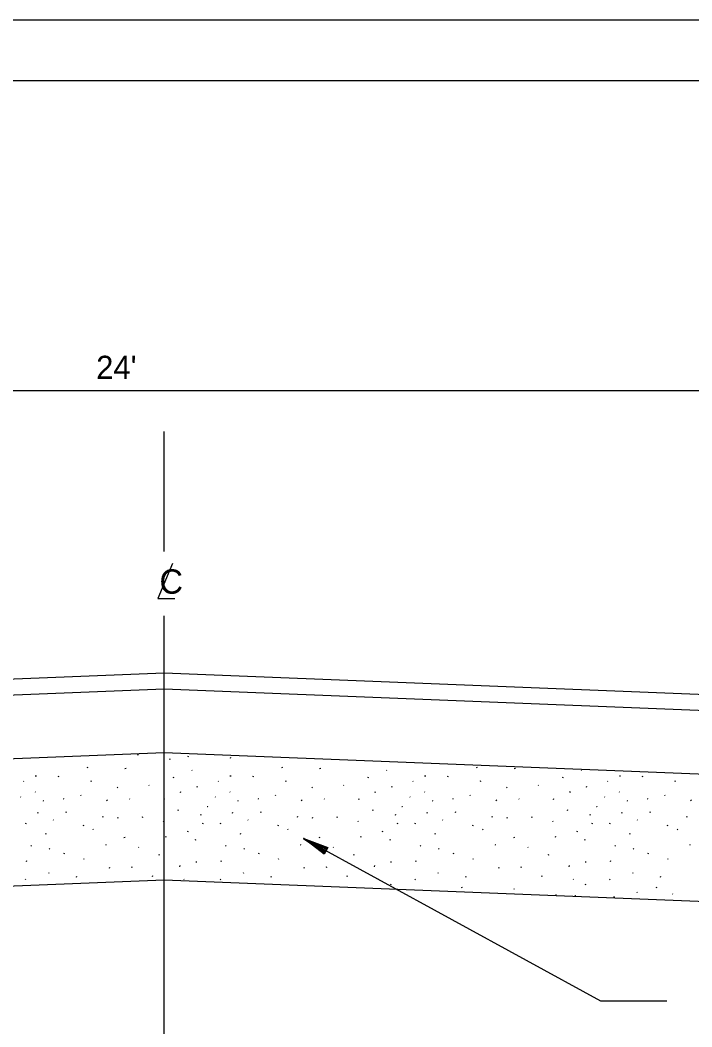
# Model space of a CAD drawing. Extents: x 29.7 to 46.4, y -39.2 to -28.2.
# Drawn here: x 40.593 to 43.008, y -31.812 to -28.193 of the extents above; entities that cross this region are included whole.
import ezdxf

# ---------------------------------------------------------------- set-up
doc = ezdxf.new("R2010")
doc.units = 0
for name, color, linetype in [('Level 11', 7, 'Continuous'), ('Level 6', 7, 'Continuous'), ('Level 60', 7, 'Continuous'), ('Level 8', 7, 'Continuous'), ('Level 9', 7, 'Continuous')]:
    doc.layers.add(name, color=color, linetype=linetype)

msp = doc.modelspace()

# ---------------------------------------------------------------- linework, layer by layer
at = {"layer": 'Level 11'}
msp.add_line((38.3762, -29.5241), (43.845, -29.5241), dxfattribs=at)
at = {"layer": 'Level 6'}
for p, q in [((41.1106, -30.1026), (41.1106, -29.672)), ((41.1106, -31.9659), (41.1106, -30.334)), ((41.1106, -30.5401), (38.3762, -30.6495)), ((43.845, -30.6495), (41.1106, -30.5401)), ((41.1106, -30.5974), (38.3762, -30.7068)), ((43.845, -30.7068), (41.1106, -30.5974)), ((41.1106, -30.8264), (38.3762, -30.9358)), ((41.0156, -30.8355), (41.0169, -30.8319)), ((43.845, -30.9358), (41.1106, -30.8264)), ((40.6492, -30.8457), (40.6495, -30.8449)), ((41.133, -30.8493), (41.1293, -30.8501)), ((41.1972, -30.8406), (41.1984, -30.837)), ((41.3492, -30.8457), (41.3505, -30.8421)), ((40.8362, -30.8798), (40.8324, -30.8806)), ((40.9736, -30.8832), (40.9698, -30.884)), ((41.2118, -30.8904), (41.21, -30.8886)), ((41.5362, -30.8798), (41.5324, -30.8806)), ((41.6736, -30.8832), (41.6698, -30.884)), ((41.9118, -30.8904), (41.91, -30.8886)), ((42.2362, -30.8798), (42.2324, -30.8806)), ((42.3736, -30.8832), (42.3698, -30.884)), ((42.6118, -30.8904), (42.61, -30.8886)), ((40.6067, -30.9301), (40.6049, -30.9283)), ((40.6513, -30.9103), (40.6475, -30.9111)), ((40.7307, -30.9134), (40.7319, -30.9098)), ((40.8498, -30.9289), (40.846, -30.9297)), ((41.0574, -30.9446), (41.0556, -30.9427)), ((41.1446, -30.9168), (41.1458, -30.9131)), ((41.3067, -30.9301), (41.3049, -30.9283)), ((41.3513, -30.9103), (41.3475, -30.9111)), ((41.4307, -30.9134), (41.4319, -30.9098)), ((41.5498, -30.9289), (41.546, -30.9297)), ((41.7574, -30.9446), (41.7556, -30.9427)), ((41.8446, -30.9168), (41.8458, -30.9131)), ((42.0067, -30.9301), (42.0049, -30.9283)), ((42.0513, -30.9103), (42.0475, -30.9111)), ((42.1307, -30.9134), (42.1319, -30.9098)), ((42.2498, -30.9289), (42.246, -30.9297)), ((42.4574, -30.9446), (42.4556, -30.9427)), ((42.5446, -30.9168), (42.5458, -30.9131)), ((42.7067, -30.9301), (42.7049, -30.9283)), ((42.7513, -30.9103), (42.7475, -30.9111)), ((42.8307, -30.9134), (42.8319, -30.9098)), ((42.9498, -30.9289), (42.946, -30.9297)), ((40.6486, -30.9683), (40.6468, -30.9664)), ((40.8126, -30.981), (40.8108, -30.9792)), ((40.9439, -30.9519), (40.9421, -30.9501)), ((41.17, -30.9693), (41.1713, -30.9656)), ((41.2295, -30.9501), (41.2307, -30.9464)), ((41.3486, -30.9683), (41.3468, -30.9664)), ((41.5126, -30.981), (41.5108, -30.9792)), ((41.6439, -30.9519), (41.6421, -30.9501)), ((41.87, -30.9693), (41.8713, -30.9656)), ((41.9295, -30.9501), (41.9307, -30.9464)), ((42.0486, -30.9683), (42.0468, -30.9664)), ((42.2126, -30.981), (42.2108, -30.9792)), ((42.3439, -30.9519), (42.3421, -30.9501)), ((42.57, -30.9693), (42.5713, -30.9656)), ((42.6295, -30.9501), (42.6307, -30.9464)), ((42.7486, -30.9683), (42.7468, -30.9664)), ((42.9126, -30.981), (42.9108, -30.9792)), ((40.5958, -30.9865), (40.5939, -30.9846)), ((40.6778, -31.001), (40.6759, -30.9992)), ((40.7507, -30.9937), (40.7488, -30.9919)), ((40.9074, -30.9974), (40.9038, -30.9992)), ((40.9876, -30.9937), (40.9858, -30.9919)), ((41.1107, -30.9946), (41.1119, -30.991)), ((41.2958, -30.9865), (41.2939, -30.9846)), ((41.3778, -31.001), (41.3759, -30.9992)), ((41.4507, -30.9937), (41.4488, -30.9919)), ((41.6074, -30.9974), (41.6038, -30.9992)), ((41.6876, -30.9937), (41.6858, -30.9919)), ((41.8107, -30.9946), (41.8119, -30.991)), ((41.9958, -30.9865), (41.9939, -30.9846)), ((42.0778, -31.001), (42.0759, -30.9992)), ((42.1507, -30.9937), (42.1488, -30.9919)), ((42.3074, -30.9974), (42.3038, -30.9992)), ((42.3876, -30.9937), (42.3858, -30.9919)), ((42.5107, -30.9946), (42.5119, -30.991)), ((42.6958, -30.9865), (42.6939, -30.9846)), ((42.7778, -31.001), (42.7759, -30.9992)), ((42.8507, -30.9937), (42.8488, -30.9919)), ((43.0074, -30.9974), (43.0038, -30.9992)), ((40.6561, -31.0441), (40.6573, -31.0405)), ((40.7579, -31.0408), (40.7591, -31.0371)), ((41.1616, -31.034), (41.1628, -31.0304)), ((41.243, -31.0509), (41.2442, -31.0473)), ((41.2651, -31.0192), (41.2666, -31.02)), ((41.2666, -31.02), (41.2673, -31.0209)), ((41.3561, -31.0441), (41.3573, -31.0405)), ((41.4579, -31.0408), (41.4591, -31.0371)), ((41.8616, -31.034), (41.8628, -31.0304)), ((41.943, -31.0509), (41.9442, -31.0473)), ((41.9651, -31.0192), (41.9666, -31.02)), ((41.9666, -31.02), (41.9673, -31.0209)), ((42.0561, -31.0441), (42.0573, -31.0405)), ((42.1579, -31.0408), (42.1591, -31.0371)), ((42.5616, -31.034), (42.5628, -31.0304)), ((42.643, -31.0509), (42.6442, -31.0473)), ((42.6651, -31.0192), (42.6666, -31.02)), ((42.6666, -31.02), (42.6673, -31.0209)), ((42.7561, -31.0441), (42.7573, -31.0405)), ((42.8579, -31.0408), (42.8591, -31.0371)), ((40.6136, -31.0819), (40.6149, -31.0783)), ((40.7131, -31.0691), (40.7113, -31.0673)), ((40.8206, -31.0887), (40.8218, -31.0851)), ((40.8902, -31.0577), (40.8914, -31.0541)), ((40.9444, -31.0616), (40.9456, -31.058)), ((41.0346, -31.0585), (41.0309, -31.0593)), ((41.11, -31.0742), (41.1082, -31.0724)), ((41.2498, -31.0814), (41.2511, -31.0778)), ((41.3136, -31.0819), (41.3149, -31.0783)), ((41.4131, -31.0691), (41.4113, -31.0673)), ((41.5206, -31.0887), (41.5218, -31.0851)), ((41.5902, -31.0577), (41.5914, -31.0541)), ((41.6444, -31.0616), (41.6456, -31.058)), ((41.7346, -31.0585), (41.7309, -31.0593)), ((41.81, -31.0742), (41.8082, -31.0724)), ((41.9498, -31.0814), (41.9511, -31.0778)), ((42.0136, -31.0819), (42.0149, -31.0783)), ((42.1131, -31.0691), (42.1113, -31.0673)), ((42.2206, -31.0887), (42.2218, -31.0851)), ((42.2902, -31.0577), (42.2914, -31.0541)), ((42.3444, -31.0616), (42.3456, -31.058)), ((42.4346, -31.0585), (42.4309, -31.0593)), ((42.51, -31.0742), (42.5082, -31.0724)), ((42.6498, -31.0814), (42.6511, -31.0778)), ((42.7136, -31.0819), (42.7149, -31.0783)), ((42.8131, -31.0691), (42.8113, -31.0673)), ((42.9206, -31.0887), (42.9218, -31.0851)), ((42.9902, -31.0577), (42.9914, -31.0541)), ((40.6849, -31.1192), (40.6861, -31.1156)), ((40.8573, -31.103), (40.8554, -31.1012)), ((41.1174, -31.1293), (41.1186, -31.1257)), ((41.1955, -31.1107), (41.1967, -31.1071)), ((41.3849, -31.1192), (41.3861, -31.1156)), ((41.5573, -31.103), (41.5554, -31.1012)), ((41.8174, -31.1293), (41.8186, -31.1257)), ((41.8955, -31.1107), (41.8967, -31.1071)), ((42.0849, -31.1192), (42.0861, -31.1156)), ((42.2573, -31.103), (42.2554, -31.1012)), ((42.5174, -31.1293), (42.5186, -31.1257)), ((42.5955, -31.1107), (42.5967, -31.1071)), ((42.7849, -31.1192), (42.7861, -31.1156)), ((42.9573, -31.103), (42.9554, -31.1012)), ((40.6333, -31.1622), (40.6315, -31.1604)), ((40.9031, -31.1588), (40.9012, -31.157)), ((40.9702, -31.1313), (40.9664, -31.1321)), ((41.2247, -31.1397), (41.2209, -31.1406)), ((41.3333, -31.1622), (41.3315, -31.1604)), ((41.6031, -31.1588), (41.6012, -31.157)), ((41.6702, -31.1313), (41.6664, -31.1321)), ((41.9247, -31.1397), (41.9209, -31.1406)), ((42.0333, -31.1622), (42.0315, -31.1604)), ((42.3031, -31.1588), (42.3012, -31.157)), ((42.3702, -31.1313), (42.3664, -31.1321)), ((42.6247, -31.1397), (42.6209, -31.1406)), ((42.7333, -31.1622), (42.7315, -31.1604)), ((43.0031, -31.1588), (43.0012, -31.157)), ((40.6995, -31.1724), (40.6977, -31.1705)), ((40.751, -31.1903), (40.7522, -31.1866)), ((41.0201, -31.1673), (41.0183, -31.1655)), ((41.094, -31.1939), (41.0903, -31.1947)), ((41.3995, -31.1724), (41.3977, -31.1705)), ((41.451, -31.1903), (41.4522, -31.1866)), ((41.7201, -31.1673), (41.7183, -31.1655)), ((41.794, -31.1939), (41.7903, -31.1947)), ((42.0995, -31.1724), (42.0977, -31.1705)), ((42.151, -31.1903), (42.1522, -31.1866)), ((42.4201, -31.1673), (42.4183, -31.1655)), ((42.494, -31.1939), (42.4903, -31.1947)), ((42.7995, -31.1724), (42.7977, -31.1705)), ((42.851, -31.1903), (42.8522, -31.1866)), ((40.6153, -31.2173), (40.6165, -31.2137)), ((40.8233, -31.2096), (40.8215, -31.2078)), ((41.1666, -31.236), (41.1679, -31.2323)), ((41.2281, -31.2193), (41.2243, -31.2201)), ((41.3153, -31.2173), (41.3165, -31.2137)), ((41.5233, -31.2096), (41.5215, -31.2078)), ((41.8666, -31.236), (41.8679, -31.2323)), ((41.9281, -31.2193), (41.9243, -31.2201)), ((42.0153, -31.2173), (42.0165, -31.2137)), ((42.2233, -31.2096), (42.2215, -31.2078)), ((42.5666, -31.236), (42.5679, -31.2323)), ((42.6281, -31.2193), (42.6243, -31.2201)), ((42.7153, -31.2173), (42.7165, -31.2137)), ((42.9233, -31.2096), (42.9215, -31.2078)), ((40.6978, -31.2604), (40.696, -31.2586)), ((40.7951, -31.2732), (40.7964, -31.2696)), ((40.9139, -31.2411), (40.9151, -31.2374)), ((40.9956, -31.2379), (40.9919, -31.2387)), ((41.0683, -31.2715), (41.0695, -31.2679)), ((41.3978, -31.2604), (41.396, -31.2586)), ((41.4951, -31.2732), (41.4964, -31.2696)), ((41.6139, -31.2411), (41.6151, -31.2374)), ((41.6956, -31.2379), (41.6919, -31.2387)), ((41.7683, -31.2715), (41.7695, -31.2679)), ((42.0978, -31.2604), (42.096, -31.2586)), ((42.1951, -31.2732), (42.1963, -31.2696)), ((42.3139, -31.2411), (42.3151, -31.2374)), ((42.3956, -31.2379), (42.3919, -31.2387)), ((42.4683, -31.2715), (42.4695, -31.2679)), ((42.7978, -31.2604), (42.796, -31.2586)), ((42.8951, -31.2732), (42.8963, -31.2696)), ((41.1106, -31.2844), (38.4332, -31.3916)), ((40.614, -31.2827), (40.6122, -31.2809)), ((43.788, -31.3916), (41.1106, -31.2844)), ((41.183, -31.2824), (41.1811, -31.2806)), ((41.314, -31.2827), (41.3122, -31.2809)), ((41.883, -31.2824), (41.8811, -31.2806)), ((41.9261, -31.3014), (41.9273, -31.2978)), ((42.014, -31.2827), (42.0122, -31.2809)), ((42.5829, -31.2824), (42.5811, -31.2806)), ((42.6261, -31.3014), (42.6273, -31.2978)), ((42.714, -31.2827), (42.7122, -31.2809)), ((42.1819, -31.3107), (42.1782, -31.3115)), ((42.3709, -31.3179), (42.3691, -31.3161)), ((42.5212, -31.3378), (42.5174, -31.3386)), ((42.5887, -31.3426), (42.5899, -31.3389)), ((42.8131, -31.3298), (42.8113, -31.3279)), ((42.8819, -31.3107), (42.8782, -31.3115)), ((42.9403, -31.3349), (42.9385, -31.333)), ((42.7304, -31.3446), (42.7267, -31.3464))]:
    msp.add_line(p, q, dxfattribs=at)
msp.add_lwpolyline([(41.1412, -30.1457), (41.0876, -30.2715), (41.1493, -30.2715)], dxfattribs=at)
at = {"layer": 'Level 60'}
for points in [[(29.7027, -39.1993), (46.0327, -39.1993), (46.0327, -28.1926), (29.7027, -28.1926)], [(30.3565, -28.4094), (45.7818, -28.4094), (45.7818, -38.965), (30.3565, -38.965)]]:
    msp.add_lwpolyline(points, close=True, dxfattribs=at)
at = {"layer": 'Level 8'}
msp.add_lwpolyline([(42.9185, -31.7191), (42.6805, -31.7191), (41.6123, -31.1347)], dxfattribs=at)
at = {"layer": 'Level 9'}
for p, q in [((41.6969, -31.1706), (41.6123, -31.1347)), ((41.6123, -31.1347), (41.6926, -31.1786)), ((41.6904, -31.1826), (41.6123, -31.1347)), ((41.6123, -31.1347), (41.6882, -31.1866)), ((41.6856, -31.1915), (41.6125, -31.1345)), ((41.613, -31.1344), (41.6992, -31.1666)), ((41.6948, -31.1746), (41.6163, -31.1369)), ((41.6992, -31.1666), (41.6856, -31.1915)), ((41.6882, -31.1866), (41.6948, -31.1746)), ((41.6926, -31.1786), (41.6904, -31.1826))]:
    msp.add_line(p, q, dxfattribs=at)

# ---------------------------------------------------------------- texts
at = {"layer": 'Level 11'}
msp.add_text("24'", height=0.08333, dxfattribs=at).set_placement((40.8664, -29.4825))
at = {"layer": 'Level 6'}
msp.add_text('C', height=0.0875, dxfattribs=at).set_placement((41.094, -30.2546))

doc.saveas('drawing.dxf')
